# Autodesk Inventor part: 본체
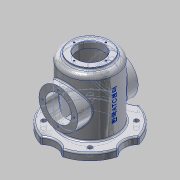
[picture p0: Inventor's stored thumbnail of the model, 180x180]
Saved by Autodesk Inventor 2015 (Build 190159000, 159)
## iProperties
Created: 2022-04
Part Number: 본체
Material: 알루미늄 6061
Document SubType Name: Modeling
Designer: User
Mass: 1517.6 g
Surface Area: 1256.99 cm^2
Volume: 562.075 cm^3
Density: 2.7 g/cm^3
Appearance: 알루미늄 - 평지
Author: User
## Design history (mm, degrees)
sketch "스케치2"
  geometry: L1 (53, 66)-(-53, 66); L2 (-53, 66)-(-53, -66); L3 (-53, -66)-(53, -66); L4 (53, -66)-(53, 66); L5 (53, 66)-(-53, -66); L6 (-53, 66)-(53, -66); 3 further points
  constraints: 12 end point, 4 midpoint, 2 parallel, 1 horizontal, 1 perpendicular
  dimensions: "d0" = 132 distance of L3.end L1.start; "d1" = 106 distance of L1.start L1.end
extrude "돌출1" new body sketch "스케치2" distance "d2" = 106; taper "d3" = 0 deg
sketch "스케치3" dims "d5" = 106
  geometry: L1 (0, 0)-(106, 0) reference; L2 (0, 0)-(0, 106) reference; L3 (0, 106)-(106, 106) reference; L4 (106, 0)-(106, 106) reference; 4 further points
  constraints: 2 midpoint, 2 vertical alignment, 2 other
extrude "돌출2" cut sketch "스케치3" stored distance "d6" = 106; taper "d7" = 0 deg
sketch "스케치4"
  geometry: C1 r 40 at (0, 0); 1 further point
  constraints: 1 centre point, 1 vertical alignment
  dimensions: "d8" = 80 diameter of C1; "d9" = 53 distance of point (0, -53) C1.centre
extrude "돌출3" join sketch "스케치4" distance "d10" = 5; taper "d11" = 0 deg
sketch "스케치5"
  geometry: C1 r 27 at (0, 0); 1 further point
  constraints: 1 centre point, 1 vertical alignment
  dimensions: "d12" = 54 diameter of C1; "d13" = 53 distance of point (0, -53) C1.centre
extrude "돌출4" cut sketch "스케치5" distance "d14" = 13; taper "d15" = 0 deg
chamfer "모따기1" distance "d16" = 1; stored, may be unused: second distance "d17" = 2, angle "d18" = 45 deg
sketch "스케치6"
  geometry: C1 r 45 at (0, 0); 1 further point
  constraints: 1 centre point, 1 vertical alignment
  dimensions: "d19" = 90 diameter of C1; "d20" = 53 distance of C1.centre point (0, -53)
extrude "돌출5" cut sketch "스케치6" distance "d21" = 124; taper "d22" = 0 deg
node "작업 평면1"
node "작업 평면2"
sketch "스케치7"
  geometry: L1 (-53, -66)-(53, -66) reference; C1 r 40 at (0, 2); 1 further point
  constraints: 1 centre point, 1 vertical alignment
  dimensions: "d25" = 80 diameter of C1; "d26" = 68 distance from line of L1 C1.centre
extrude "돌출6" join sketch "스케치7" stored distance "d27" = 124; taper "d28" = 0 deg
sketch "스케치8"
  geometry: L1 (-53, -68)-(53, -68) reference; C1 r 27 at (0, 0); 1 further point
  constraints: 1 centre point, 1 vertical alignment
  dimensions: "d29" = 54 diameter of C1; "d30" = 68 distance from line of L1 C1.centre
extrude "돌출7" cut sketch "스케치8" stored distance "d31" = 124; taper "d32" = 0 deg
sketch "스케치9" dims "d33" = 65
  geometry: L1 (-53, -68)-(53, -68) reference; L2 (0, 0)-(0, 32.5); 2 further points
  constraints: 2 end point, 2 vertical alignment, 1 coincident, 1 vertical, 2 other
  dimensions: "d34" = 68 distance from line of L1 L2.start
hole "구멍1" sketch "스케치9" at (0, 32.5) diameter "d35" = 3.242; stored, may be unused: countersink angle "d39" = 90 deg, drill point angle "d41" = 118 deg; dims "d36" = 8, "d37" = 4, "d38" = 2, "d40" = 10
node "작업 평면3"
sketch "스케치10"
  geometry: L1 (-53, -66)-(53, -66) reference; C1 r 40 at (0, 2); 1 further point
  constraints: 1 centre point, 1 vertical alignment
  dimensions: "d46" = 80 diameter of C1; "d47" = 68 distance from line of L1 C1.centre
extrude "돌출8" join sketch "스케치10" stored distance "d48" = 124; taper "d49" = 0 deg
sketch "스케치11"
  geometry: L1 (53, 68)-(-53, 68) reference; C1 r 27 at (0, 0); 1 further point
  constraints: 1 centre point, 1 vertical alignment
  dimensions: "d50" = 54 diameter of C1; "d51" = 68 distance from line of L1 C1.centre
extrude "돌출9" cut sketch "스케치11" stored distance "d52" = 124; taper "d53" = 0 deg
sketch "스케치12" dims "d54" = 65
  geometry: L1 (53, 68)-(-53, 68) reference; L2 (0, 0)-(0, -32.5); 2 further points
  constraints: 2 end point, 2 vertical alignment, 1 coincident, 1 vertical, 2 other
  dimensions: "d55" = 68 distance from line of L1 L2.start
hole "구멍2" sketch "스케치12" at (0, -32.5) diameter "d56" = 3.242; stored, may be unused: countersink angle "d60" = 90 deg, drill point angle "d62" = 118 deg; dims "d57" = 8, "d58" = 4, "d59" = 2, "d61" = 10
sketch "스케치13" dims "d66" = 65
  geometry: L1 (0, 0)-(0, -32.5); 2 further points
  constraints: 2 end point, 2 vertical alignment, 1 coincident, 1 vertical, 2 other
  dimensions: "d67" = 53 distance of L1.start point (0, -53)
hole "구멍3" sketch "스케치13" at (0, -32.5) diameter "d68" = 3.242; stored, may be unused: countersink angle "d72" = 90 deg, drill point angle "d74" = 118 deg; dims "d69" = 8, "d70" = 4, "d71" = 2, "d73" = 10
node "작업 평면4"
sketch "스케치14"
  geometry: C1 r 28 at (0, 53) reference; A1 r 30 centre (0, -47) between (21.541, -26.12) and (-21.541, -26.12); A2 r 30 centre (-100, 53) between (-79.12, 31.459) and (-79.12, 74.541); A3 r 30 centre (0, 153) between (-21.541, 132.12) and (21.541, 132.12); A4 r 30 centre (100, 53) between (79.12, 74.541) and (79.12, 31.459); A5 r 82 centre (0, 53) between (-79.12, 31.459) and (-21.541, -26.12); A6 r 82 centre (0, 53) between (-21.541, 132.12) and (-79.12, 74.541); A7 r 82 centre (0, 53) between (21.541, -26.12) and (79.12, 31.459); A8 r 82 centre (0, 53) between (79.12, 74.541) and (21.541, 132.12); 1 further point
  constraints: 16 point on circle, 8 centre point, 2 horizontal alignment, 2 vertical alignment, 1 coincident
  dimensions: "d80" = 60 diameter of A1; "d81" = 60 diameter of A2; "d82" = 60 diameter of A3; "d83" = 60 diameter of A4; "d84" = 100 distance of C1.centre A1.centre; "d85" = 100 distance of A3.centre C1.centre; "d86" = 100 distance of A4.centre C1.centre; "d87" = 100 distance of A2.centre C1.centre; "d88" = 82 radius of A7; "d89" = 82 radius of A8; "d90" = 82 radius of A6; "d91" = 82 radius of A5
extrude "돌출10" join sketch "스케치14" distance "d92" = 14; taper "d93" = 0 deg
sketch "스케치15"
  geometry: C1 r 45 at (0, 53); 1 further point
  constraints: 1 centre point, 1 vertical alignment
  dimensions: "d94" = 90 diameter of C1; "d95" = 53 distance of C1.centre point (0, 0)
extrude "돌출11" cut sketch "스케치15" distance "d96" = 14; taper "d97" = 0 deg
sketch "스케치16" dims "d98" = 135
  geometry: L1 (0, 53)-(-47.73, 5.27); L2 (0, 53)-(-47.73, 100.73); L3 (0, 53)-(47.73, 5.27); L4 (0, 53)-(47.73, 100.73); L5 (0, 53)-(0, -14.5); L6 (0, 53)-(0, 120.5); L7 (0, 53)-(-67.5, 53); L8 (0, 53)-(67.5, 53); C1 r 4.5 at (-47.73, 5.27); C2 r 4.5 at (-47.73, 100.73); C3 r 4.5 at (47.73, 100.73); C4 r 4.5 at (47.73, 5.27); 1 further point
  constraints: 16 end point, 4 centre point, 4 coincident, 2 horizontal, 2 vertical, 1 vertical alignment, 10 other
  dimensions: "d99" = 53 distance of L1.start point (0, 0); "d100" = 45 deg angle of L2 L7; "d101" = 45 deg angle of L7 L1; "d103" = 45 deg angle of L8 L3; "d104" = 45 deg angle of L8 L4; "d105" = 9 diameter of C1; "d106" = 9 diameter of C2; "d107" = 9 diameter of C3; "d108" = 9 diameter of C4
extrude "돌출12" cut sketch "스케치16" distance "d109" = 14; taper "d110" = 0 deg
fillet "모깎기1" dims "d111" = 3
fillet "모깎기2" dims "d112" = 3
fillet "모깎기3" dims "d113" = 3
fillet "모깎기4" dims "d114" = 10
node "작업 평면5"
sketch "스케치17"
  geometry: L1 (32.643, -66)-(73.357, -66) reference; L2 (-12, 42)-(-12, -38) reference; 2 further points
  constraints: 1 other
  dimensions: "d116" = 70 distance from line of L1 point (50, 4); "d117" = 62 distance from line of point (50, 4) L2
feature "엠보싱1" sketch "스케치17" dims "d0" = 132, "d1" = 106, "d118" = 0.5, "d119" = 0
node "솔리드1"
pattern_circular "원형 패턴1" dims angle "d43" = 360 deg
pattern_circular "원형 패턴2" dims angle "d64" = 360 deg
pattern_circular "원형 패턴3" dims angle "d76" = 360 deg
other parameters: "d24" = -62, "d45" = 62, "d78" = -66, "d79" = 164, "d115" = 100.75
